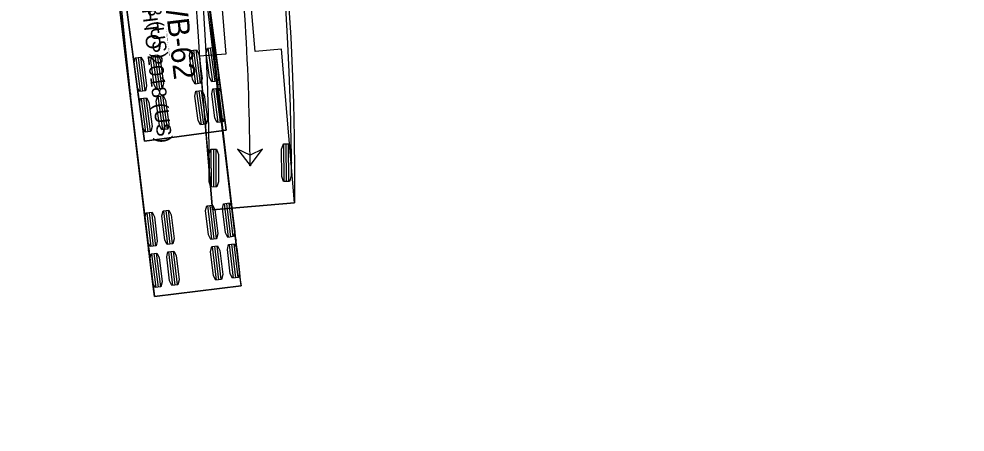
# Model space of a CAD drawing. Extents: x 1600240 to 1604759, y 285789 to 289704.
# Drawn here: x 1601615.8 to 1601707.8, y 286571 to 286611.2 of the extents above; entities that cross this region are included whole.
import ezdxf

# ---------------------------------------------------------------- set-up
doc = ezdxf.new("R2010")
doc.units = 0
for name, color, linetype in [('MT_P_CL_Double_Solid', 7, 'Continuous'), ('MT_X_Edge_Line', 7, 'Continuous'), ('TR_Turning_Path3', 7, 'Continuous'), ('TR_Turning_Path4', 7, 'Continuous')]:
    doc.layers.add(name, color=color, linetype=linetype)

msp = doc.modelspace()

# ---------------------------------------------------------------- linework, layer by layer
at = {"layer": 'MT_P_CL_Double_Solid'}
for p, q in [((1601635.924, 286600.387), (1601631.565, 286633.098)), ((1601623.635, 286632.041), (1601627.995, 286599.33)), ((1601634.166, 286608.375), (1601634.602, 286605.104)), ((1601634.393, 286608.405), (1601634.829, 286605.134)), ((1601634.621, 286608.436), (1601635.057, 286605.165)), ((1601627.145, 286607.439), (1601627.581, 286604.168)), ((1601627.372, 286607.47), (1601627.808, 286604.198)), ((1601627.599, 286607.5), (1601628.035, 286604.229)), ((1601628.781, 286607.657), (1601629.217, 286604.386)), ((1601629.008, 286607.688), (1601629.444, 286604.416)), ((1601629.235, 286607.718), (1601629.671, 286604.447)), ((1601632.531, 286608.157), (1601632.967, 286604.886)), ((1601632.758, 286608.187), (1601633.194, 286604.916)), ((1601632.985, 286608.218), (1601633.421, 286604.947)), ((1601629.309, 286603.692), (1601629.745, 286600.421)), ((1601629.536, 286603.723), (1601629.972, 286600.452)), ((1601629.763, 286603.753), (1601630.199, 286600.482)), ((1601633.059, 286604.192), (1601633.495, 286600.921)), ((1601633.286, 286604.222), (1601633.722, 286600.951)), ((1601633.514, 286604.253), (1601633.949, 286600.982)), ((1601634.695, 286604.41), (1601635.131, 286601.139)), ((1601634.922, 286604.44), (1601635.358, 286601.169)), ((1601635.149, 286604.471), (1601635.585, 286601.2)), ((1601627.673, 286603.474), (1601628.109, 286600.203)), ((1601627.901, 286603.505), (1601628.337, 286600.234)), ((1601628.128, 286603.535), (1601628.564, 286600.264)), ((1601627.995, 286599.33), (1601635.924, 286600.387))]:
    msp.add_line(p, q, dxfattribs=at)
for points in [[(1601627.804, 286600.759), (1601621.95, 286644.686), (1601621.785, 286646.064), (1601621.198, 286651.595), (1601620.682, 286656.836), (1601620.199, 286662.153), (1601619.748, 286667.57), (1601619.644, 286669.39), (1601619.607, 286670.84)], [(1601633.596, 286671.411), (1601633.041, 286669.939), (1601632.543, 286668.446), (1601632.019, 286666.63), (1601631.64, 286665.099), (1601631.254, 286663.244), (1601630.894, 286661.06), (1601630.624, 286658.856), (1601630.44, 286656.637), (1601630.333, 286654.405), (1601630.297, 286652.164), (1601630.333, 286649.594), (1601630.438, 286647.019), (1601630.624, 286644.118), (1601630.866, 286641.217), (1601631.215, 286637.672), (1601631.642, 286633.807), (1601632.214, 286628.979), (1601633.671, 286617.403), (1601635.924, 286600.387), (1601627.995, 286599.33), (1601627.804, 286600.759)], [(1601635.33, 286604.848), (1601634.89, 286608.147), (1601634.453, 286611.443), (1601634.019, 286614.736), (1601633.59, 286618.029), (1601633.168, 286621.32), (1601632.752, 286624.611), (1601632.426, 286627.244)], [(1601627.4, 286603.791), (1601626.96, 286607.092), (1601626.522, 286610.393), (1601626.087, 286613.696), (1601625.657, 286617.001), (1601625.232, 286620.309), (1601624.814, 286623.618), (1601624.486, 286626.267)]]:
    msp.add_lwpolyline(points, dxfattribs=at)
for points in [[(1601634.11, 286608.368), (1601634.677, 286608.443), (1601634.909, 286608.008), (1601635.223, 286605.653), (1601635.113, 286605.172), (1601634.546, 286605.096), (1601634.314, 286605.532), (1601634, 286607.887)], [(1601627.089, 286607.432), (1601627.656, 286607.507), (1601627.888, 286607.072), (1601628.201, 286604.717), (1601628.092, 286604.236), (1601627.525, 286604.161), (1601627.293, 286604.596), (1601626.979, 286606.951)], [(1601628.724, 286607.65), (1601629.291, 286607.725), (1601629.523, 286607.29), (1601629.837, 286604.935), (1601629.727, 286604.454), (1601629.16, 286604.379), (1601628.928, 286604.814), (1601628.614, 286607.169)], [(1601632.474, 286608.15), (1601633.041, 286608.225), (1601633.273, 286607.79), (1601633.587, 286605.435), (1601633.477, 286604.954), (1601632.91, 286604.879), (1601632.679, 286605.314), (1601632.365, 286607.669)], [(1601629.253, 286603.685), (1601629.82, 286603.76), (1601630.052, 286603.325), (1601630.365, 286600.97), (1601630.256, 286600.489), (1601629.689, 286600.414), (1601629.457, 286600.849), (1601629.143, 286603.204)], [(1601633.003, 286604.185), (1601633.57, 286604.26), (1601633.802, 286603.825), (1601634.116, 286601.47), (1601634.006, 286600.989), (1601633.439, 286600.914), (1601633.207, 286601.349), (1601632.893, 286603.704)], [(1601634.638, 286604.403), (1601635.205, 286604.478), (1601635.437, 286604.043), (1601635.751, 286601.688), (1601635.641, 286601.207), (1601635.074, 286601.132), (1601634.842, 286601.567), (1601634.529, 286603.922)], [(1601627.617, 286603.467), (1601628.184, 286603.542), (1601628.416, 286603.107), (1601628.73, 286600.752), (1601628.62, 286600.271), (1601628.053, 286600.196), (1601627.821, 286600.631), (1601627.507, 286602.986)]]:
    msp.add_lwpolyline(points, close=True, dxfattribs=at)
for centre in [(1601635.33, 286604.848), (1601627.4, 286603.791)]:
    msp.add_circle(centre, 0.0417, dxfattribs=at)
at = {"layer": 'MT_X_Edge_Line'}
msp.add_arc((1602837.866, 287782.942), 1921, 229.7619, 229.7619, dxfattribs=at)
at = {"layer": 'TR_Turning_Path3'}
for p, q in [((1601637.399, 286585.24), (1601631.682, 286632.898)), ((1601623.243, 286631.886), (1601628.959, 286584.228)), ((1601634.108, 286593.054), (1601634.501, 286589.777)), ((1601634.335, 286593.081), (1601634.728, 286589.804)), ((1601634.563, 286593.108), (1601634.956, 286589.832)), ((1601635.746, 286593.25), (1601636.139, 286589.974)), ((1601635.973, 286593.277), (1601636.366, 286590.001)), ((1601636.201, 286593.305), (1601636.594, 286590.028)), ((1601628.216, 286592.347), (1601628.609, 286589.07)), ((1601628.444, 286592.374), (1601628.837, 286589.098)), ((1601628.671, 286592.402), (1601629.064, 286589.125)), ((1601629.855, 286592.543), (1601630.248, 286589.267)), ((1601630.082, 286592.571), (1601630.475, 286589.294)), ((1601630.31, 286592.598), (1601630.703, 286589.322)), ((1601634.584, 286589.082), (1601634.977, 286585.806)), ((1601634.811, 286589.109), (1601635.204, 286585.833)), ((1601635.039, 286589.137), (1601635.432, 286585.86)), ((1601636.222, 286589.279), (1601636.615, 286586.002)), ((1601636.45, 286589.306), (1601636.843, 286586.029)), ((1601636.677, 286589.333), (1601637.07, 286586.057)), ((1601628.693, 286588.375), (1601629.086, 286585.099)), ((1601628.92, 286588.403), (1601629.313, 286585.126)), ((1601629.148, 286588.43), (1601629.541, 286585.154)), ((1601630.331, 286588.572), (1601630.724, 286585.295)), ((1601630.559, 286588.599), (1601630.952, 286585.323)), ((1601630.786, 286588.627), (1601631.179, 286585.35)), ((1601628.959, 286584.228), (1601637.399, 286585.24))]:
    msp.add_line(p, q, dxfattribs=at)
for points in [[(1601628.788, 286585.657), (1601622.925, 286634.563), (1601622.405, 286639.474), (1601621.992, 286644.416), (1601620.944, 286653.156), (1601620.831, 286654.263), (1601620.727, 286655.731), (1601620.676, 286657.19), (1601620.707, 286661.917), (1601620.793, 286665.212), (1601620.912, 286668.155), (1601621, 286669.627), (1601621.142, 286671.084)], [(1601626.64, 286603.897), (1601626.494, 286605.221), (1601626.143, 286608.515), (1601625.815, 286611.777), (1601625.519, 286614.992), (1601625.264, 286618.142), (1601625.059, 286621.219), (1601624.908, 286624.272), (1601624.821, 286627.304), (1601624.807, 286630.308), (1601624.871, 286633.282), (1601625.02, 286636.221), (1601625.259, 286639.119), (1601625.591, 286641.974), (1601626.019, 286644.782), (1601626.545, 286647.537), (1601627.171, 286650.235), (1601627.668, 286652.089)], [(1601635.088, 286604.837), (1601634.944, 286606.147), (1601634.597, 286609.397), (1601634.275, 286612.598), (1601633.987, 286615.732), (1601633.74, 286618.778), (1601633.544, 286621.724), (1601633.401, 286624.616), (1601633.32, 286627.459), (1601633.307, 286630.252), (1601633.366, 286632.99), (1601633.503, 286635.672), (1601633.719, 286638.296), (1601634.017, 286640.86), (1601634.399, 286643.36), (1601634.865, 286645.796), (1601635.415, 286648.164), (1601635.849, 286649.781)], [(1601634.242, 286612.937), (1601634.733, 286608.1), (1601635.374, 286602.297), (1601637.247, 286586.51), (1601637.298, 286585.801), (1601637.399, 286585.24), (1601628.959, 286584.228), (1601628.788, 286585.657)], [(1601636.863, 286589.708), (1601636.467, 286593.015), (1601636.073, 286596.308), (1601635.686, 286599.592), (1601635.309, 286602.872), (1601635.088, 286604.837)], [(1601628.424, 286588.696), (1601628.027, 286592.004), (1601627.633, 286595.305), (1601627.244, 286598.606), (1601626.863, 286601.912), (1601626.64, 286603.897)]]:
    msp.add_lwpolyline(points, dxfattribs=at)
for points in [[(1601634.051, 286593.047), (1601634.619, 286593.115), (1601634.845, 286592.677), (1601635.128, 286590.318), (1601635.012, 286589.838), (1601634.444, 286589.77), (1601634.218, 286590.209), (1601633.935, 286592.568)], [(1601635.689, 286593.243), (1601636.257, 286593.311), (1601636.483, 286592.873), (1601636.766, 286590.514), (1601636.65, 286590.035), (1601636.082, 286589.967), (1601635.856, 286590.405), (1601635.573, 286592.764)], [(1601628.16, 286592.34), (1601628.728, 286592.408), (1601628.954, 286591.97), (1601629.237, 286589.611), (1601629.121, 286589.132), (1601628.553, 286589.064), (1601628.327, 286589.502), (1601628.044, 286591.861)], [(1601629.798, 286592.537), (1601630.366, 286592.605), (1601630.592, 286592.167), (1601630.875, 286589.808), (1601630.759, 286589.328), (1601630.191, 286589.26), (1601629.965, 286589.698), (1601629.682, 286592.057)], [(1601634.527, 286589.075), (1601635.095, 286589.143), (1601635.322, 286588.705), (1601635.604, 286586.346), (1601635.488, 286585.867), (1601634.92, 286585.799), (1601634.694, 286586.237), (1601634.411, 286588.596)], [(1601636.166, 286589.272), (1601636.734, 286589.34), (1601636.96, 286588.902), (1601637.243, 286586.543), (1601637.127, 286586.063), (1601636.559, 286585.995), (1601636.333, 286586.433), (1601636.05, 286588.793)], [(1601628.636, 286588.369), (1601629.204, 286588.437), (1601629.43, 286587.999), (1601629.713, 286585.64), (1601629.597, 286585.16), (1601629.029, 286585.092), (1601628.803, 286585.53), (1601628.52, 286587.889)], [(1601630.275, 286588.565), (1601630.843, 286588.633), (1601631.069, 286588.195), (1601631.352, 286585.836), (1601631.236, 286585.357), (1601630.668, 286585.289), (1601630.441, 286585.727), (1601630.159, 286588.086)]]:
    msp.add_lwpolyline(points, close=True, dxfattribs=at)
for centre in [(1601635.088, 286604.837), (1601635.088, 286604.837), (1601626.64, 286603.897), (1601626.64, 286603.897), (1601636.863, 286589.708), (1601628.424, 286588.696)]:
    msp.add_circle(centre, 0.0417, dxfattribs=at)
at = {"layer": 'TR_Turning_Path4'}
for p, q in [((1601638.763, 286608.044), (1601637.87, 286618.607)), ((1601635.013, 286618.365), (1601635.907, 286607.803)), ((1601641.321, 286608.261), (1601638.763, 286608.044)), ((1601642.586, 286593.314), (1601641.321, 286608.261)), ((1601635.907, 286607.803), (1601633.349, 286607.586)), ((1601633.349, 286607.586), (1601634.614, 286592.64)), ((1601641.577, 286595.391), (1601641.551, 286599.058)), ((1601641.806, 286595.393), (1601641.78, 286599.059)), ((1601642.035, 286595.394), (1601642.009, 286599.061)), ((1601634.512, 286594.866), (1601634.493, 286598.533)), ((1601634.741, 286594.867), (1601634.722, 286598.534)), ((1601634.97, 286594.868), (1601634.952, 286598.535)), ((1601634.614, 286592.64), (1601642.586, 286593.314)), ((1601642.586, 286593.314), (1601642.586, 286593.314))]:
    msp.add_line(p, q, dxfattribs=at)
for points in [[(1601623.417, 286652.845), (1601624.145, 286650.831), (1601625.393, 286647.518), (1601626.656, 286644.247), (1601627.896, 286641.005), (1601629.077, 286637.784), (1601630.163, 286634.572), (1601631.117, 286631.362), (1601631.903, 286628.152), (1601632.485, 286624.944), (1601632.872, 286621.697), (1601633.201, 286618.417), (1601633.487, 286615.134), (1601633.729, 286611.847), (1601633.927, 286608.557), (1601634.08, 286605.264), (1601634.19, 286601.971), (1601634.255, 286598.675), (1601634.274, 286596.698)], [(1601631.252, 286652.811), (1601631.998, 286651.098), (1601633.256, 286648.219), (1601634.51, 286645.304), (1601635.734, 286642.34), (1601636.901, 286639.314), (1601637.979, 286636.214), (1601638.936, 286633.033), (1601639.738, 286629.768), (1601640.346, 286626.419), (1601640.756, 286623.029), (1601641.102, 286619.645), (1601641.404, 286616.257), (1601641.66, 286612.865), (1601641.87, 286609.469), (1601642.035, 286606.072), (1601642.155, 286602.672), (1601642.229, 286599.27), (1601642.252, 286597.229)], [(1601642.003, 286612.737), (1601642.209, 286609.396), (1601642.357, 286606.385), (1601642.48, 286603.044), (1601642.558, 286599.696), (1601642.592, 286596.349), (1601642.586, 286593.314), (1601634.614, 286592.64), (1601633.368, 286607.368), (1601633.274, 286609.024), (1601632.925, 286614.317)], [(1601638.263, 286596.963), (1601639.47, 286598.557), (1601638.256, 286597.963), (1601637.035, 286598.542), (1601638.263, 286596.963)]]:
    msp.add_lwpolyline(points, dxfattribs=at)
for points in [[(1601642.092, 286595.395), (1601641.52, 286595.391), (1601641.344, 286595.903), (1601641.326, 286598.543), (1601641.494, 286599.057), (1601642.066, 286599.061), (1601642.242, 286598.549), (1601642.261, 286595.909)], [(1601635.027, 286594.869), (1601634.455, 286594.866), (1601634.28, 286595.378), (1601634.267, 286598.018), (1601634.436, 286598.532), (1601635.008, 286598.535), (1601635.183, 286598.023), (1601635.197, 286595.383)], [(1601638.263, 286596.963), (1601639.47, 286598.557), (1601638.256, 286597.963), (1601637.035, 286598.542)]]:
    msp.add_lwpolyline(points, close=True, dxfattribs=at)
for centre in [(1601642.252, 286597.229), (1601634.274, 286596.698), (1601638.263, 286596.963)]:
    msp.add_circle(centre, 0.0417, dxfattribs=at)
msp.add_arc((1601388.002, 286595.43), 250.265, 0.35089, 6.63781, dxfattribs=at)

# ---------------------------------------------------------------- texts
at = {"layer": 'MT_P_CL_Double_Solid'}
msp.add_text('AASHTO 2018 (US)', height=1.33333, rotation=277.59143, dxfattribs=at).set_placement((1601626.838, 286623.1))
at = {"layer": 'TR_Turning_Path3'}
for s, height, p in [('AASHTO 2018 (US)', 1.41667, (1601627.291, 286615.92)), ('WB-62', 2.125, (1601629.857, 286613.858)), ('(c) 2024 Transoft Solutions, Inc. All rights reserved.', 0.085, (1601630.071, 286610.286))]:
    msp.add_text(s, height=height, rotation=276.83987, dxfattribs=at).set_placement(p)

doc.saveas('drawing.dxf')
